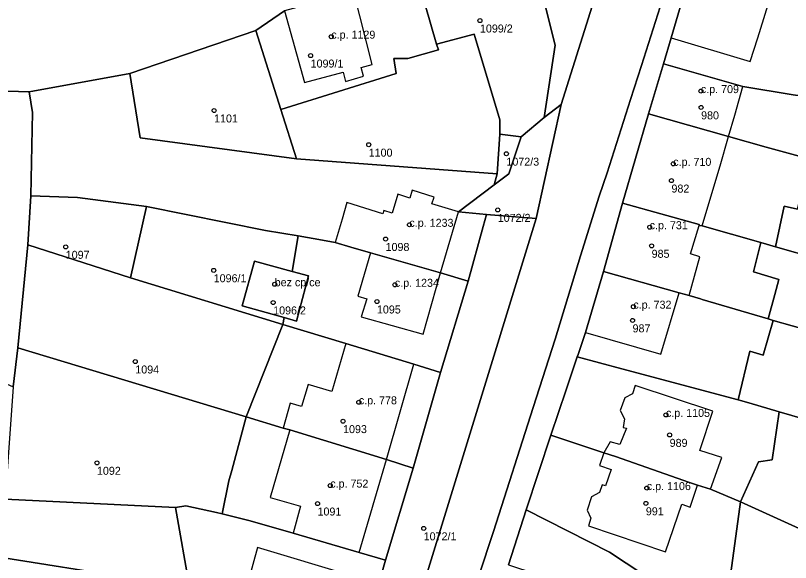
# Model space of a CAD drawing. Extents: x -878211 to -870363, y -1058464 to -1052522.
# Drawn here: x -875048.6 to -874951.8, y -1056467.9 to -1056399.5 of the extents above; entities that cross this region are included whole.
import ezdxf

# ---------------------------------------------------------------- set-up
doc = ezdxf.new("R2010")
doc.units = 0
for name, color, linetype in [('Vrstva 50', 7, 'Continuous'), ('Vrstva 51', 7, 'Continuous'), ('Vrstva 52', 7, 'Continuous')]:
    doc.layers.add(name, color=color, linetype=linetype)

msp = doc.modelspace()

# ---------------------------------------------------------------- linework, layer by layer
at = {"layer": 'Vrstva 50'}
for centre in [(-874990.58, -1056400.14994), (-875009.15, -1056402.15994), (-875011.73, -1056404.52994), (-874962.99, -1056408.95994), (-875023.79, -1056411.38994), (-874962.96, -1056410.99994), (-875004.48, -1056415.65994), (-874987.28, -1056416.78994), (-874966.44, -1056418.04994), (-874966.66, -1056420.14994), (-874988.36, -1056423.80994), (-874999.39, -1056425.66994), (-874969.38, -1056425.96994), (-875002.37, -1056427.44994), (-874969.14, -1056428.29994), (-875042.32, -1056428.42994), (-875023.84, -1056431.35994), (-875016.22, -1056433.09994), (-875001.21, -1056433.16994), (-875016.41, -1056435.37994), (-875003.45, -1056435.25994), (-874971.42, -1056435.89994), (-874971.52, -1056437.61994), (-875033.63, -1056442.75994), (-875005.71, -1056447.84994), (-874967.35, -1056449.42994), (-875007.68, -1056450.20994), (-874966.89, -1056451.92994), (-875038.42, -1056455.41994), (-875009.28, -1056458.25994), (-874969.74, -1056458.56994), (-875010.87, -1056460.50994), (-874969.86, -1056460.47994), (-874997.61, -1056463.60994)]:
    msp.add_circle(centre, 0.25, dxfattribs=at)
at = {"layer": 'Vrstva 51'}
for points in [[(-874984.08, -1056391.71), (-874981.2, -1056403.23), (-874982.58, -1056412.24), (-874980.45, -1056410.63), (-874975.13, -1056393.67), (-874976.34, -1056387.44)], [(-874927.21, -1056413.07), (-874923.91, -1056412.98), (-874926.18, -1056408.98), (-874942.27, -1056402.9), (-874949.01, -1056401.83), (-874947.24, -1056394.66), (-874952.14, -1056393.26), (-874963.08, -1056389.92), (-874966.7, -1056402.29), (-874967.66, -1056405.55), (-874957.75, -1056408.4), (-874951.48, -1056409.42), (-874947.2, -1056410.02)], [(-874984.08, -1056391.71), (-874998.25, -1056393.44), (-874997.32, -1056396.44), (-874997.44, -1056398.16), (-874995.99, -1056403.11), (-874991.31, -1056401.83), (-874988.08, -1056412.56), (-874988.12, -1056414.34), (-874985.42, -1056414.69), (-874982.58, -1056412.24), (-874981.2, -1056403.23)], [(-875015, -1056398.93), (-875018.57, -1056401.39), (-875015.44, -1056411.27), (-875001.06, -1056406.74), (-875001.34, -1056404.9), (-874999.58, -1056404.88), (-874995.78, -1056403.81), (-874995.99, -1056403.11), (-874997.44, -1056398.16), (-874997.32, -1056396.44), (-874998.25, -1056393.44), (-875002.02, -1056394.71), (-875001.89, -1056395.35), (-875006.33, -1056396.55)], [(-875018.57, -1056401.39), (-875034.3, -1056406.76), (-875033.02, -1056414.82), (-875013.49, -1056417.41), (-875015.44, -1056411.27)], [(-875013.49, -1056417.41), (-874988.44, -1056419.28), (-874988.12, -1056414.34), (-874988.08, -1056412.56), (-874991.31, -1056401.83), (-874995.99, -1056403.11), (-874995.78, -1056403.81), (-874999.58, -1056404.88), (-875001.34, -1056404.9), (-875001.06, -1056406.74), (-875015.44, -1056411.27)], [(-874947.65, -1056413.12), (-874947.2, -1056410.02), (-874951.48, -1056409.42), (-874957.75, -1056408.4), (-874967.66, -1056405.55), (-874969.53, -1056411.81), (-874959.54, -1056414.63), (-874954.84, -1056415.97), (-874950.72, -1056417.09), (-874949.95, -1056414.48), (-874949.48, -1056412.86)], [(-875017.37, -1056426.37), (-875013.27, -1056427.06), (-875010.23, -1056427.6), (-875008.66, -1056427.88), (-875006.7, -1056428.46), (-875004.26, -1056429.17), (-874995.5, -1056431.65), (-874992.07, -1056432.71), (-874990.17, -1056425.89), (-874989.75, -1056424.38), (-874993.25, -1056424.06), (-874988.8, -1056420.68), (-874988.44, -1056419.28), (-875013.49, -1056417.41), (-875033.02, -1056414.82), (-875034.3, -1056406.76), (-875046.89, -1056409.04), (-875046.48, -1056411.64), (-875046.68, -1056422.03), (-875040.87, -1056422.27), (-875032.25, -1056423.39)], [(-875046.89, -1056409.04), (-875072.36, -1056408.27), (-875075.97, -1056432.36), (-875076.17, -1056433.71), (-875048.87, -1056445.91), (-875048.32, -1056441.03), (-875047.06, -1056428.16), (-875046.68, -1056422.03), (-875046.48, -1056411.64)], [(-874986.98, -1056419.3), (-874988.8, -1056420.68), (-874993.25, -1056424.06), (-874989.75, -1056424.38), (-874983.57, -1056424.89), (-874980.45, -1056410.63), (-874982.58, -1056412.24), (-874985.42, -1056414.69)], [(-874963.22, -1056425.61), (-874963.21, -1056425.75), (-874962.81, -1056425.81), (-874955.52, -1056427.88), (-874953.65, -1056428.41), (-874952.58, -1056423.34), (-874950.93, -1056423.7), (-874950.63, -1056422.46), (-874949.3, -1056417.66), (-874950.68, -1056417.27), (-874950.72, -1056417.09), (-874954.84, -1056415.97), (-874959.54, -1056414.63), (-874969.53, -1056411.81), (-874972.76, -1056422.98)], [(-874988.44, -1056419.28), (-874988.8, -1056420.68), (-874986.98, -1056419.3), (-874985.42, -1056414.69), (-874988.12, -1056414.34)], [(-874953.65, -1056428.41), (-874932.5, -1056434.41), (-874929.49, -1056422.89), (-874950.72, -1056417.09), (-874950.68, -1056417.27), (-874949.3, -1056417.66), (-874950.63, -1056422.46), (-874950.93, -1056423.7), (-874952.58, -1056423.34)], [(-875034.25, -1056432.28), (-875032.25, -1056423.39), (-875040.87, -1056422.27), (-875046.68, -1056422.03), (-875047.06, -1056428.16)], [(-874954.58, -1056437.43), (-874953.77, -1056434.39), (-874953.27, -1056432.5), (-874956.42, -1056431.54), (-874955.52, -1056427.88), (-874962.81, -1056425.81), (-874963.21, -1056425.75), (-874963.22, -1056425.61), (-874972.76, -1056422.98), (-874975.17, -1056431.51), (-874965.68, -1056434.16), (-874964.45, -1056434.5), (-874963.05, -1056434.92), (-874962.81, -1056434.99)], [(-875014.05, -1056431.5), (-875013.27, -1056427.06), (-875017.37, -1056426.37), (-875032.25, -1056423.39), (-875034.25, -1056432.28), (-875015.2, -1056438.11), (-875015.05, -1056437.27), (-875020.29, -1056435.78), (-875018.76, -1056430.22)], [(-875005.15, -1056492.08), (-875001.65, -1056483.66), (-874983.57, -1056424.89), (-874989.75, -1056424.38), (-874990.17, -1056425.89), (-874992.07, -1056432.71), (-874995.49, -1056444.12), (-874998.92, -1056456.06), (-875002.36, -1056467.57), (-875004.97, -1056476.64), (-875007.33, -1056484.59), (-875009.05, -1056490.76), (-875012.84, -1056499.56), (-875015.72, -1056498.32), (-875017.98, -1056502.52), (-875014.85, -1056504.16), (-875019.19, -1056511.94), (-875019.42, -1056511.79), (-875024.6, -1056521.2), (-875025.16, -1056522.21), (-875025.65, -1056521.97), (-875028.12, -1056520.77), (-875035.19, -1056534.63), (-875032.55, -1056540.02)], [(-875014.05, -1056431.5), (-875011.98, -1056432.06), (-875013.51, -1056437.71), (-875015.05, -1056437.27), (-875015.2, -1056438.11), (-875007.34, -1056440.51), (-874998.84, -1056443.1), (-874995.49, -1056444.12), (-874992.07, -1056432.71), (-874995.5, -1056431.65), (-875004.26, -1056429.17), (-875006.7, -1056428.46), (-875008.66, -1056427.88), (-875010.23, -1056427.6), (-875013.27, -1056427.06)], [(-874953.97, -1056437.61), (-874934.97, -1056442.94), (-874904.61, -1056451.62), (-874902.27, -1056446.22), (-874900.82, -1056442.88), (-874932.5, -1056434.41), (-874953.65, -1056428.41), (-874955.52, -1056427.88), (-874956.42, -1056431.54), (-874953.27, -1056432.5), (-874953.77, -1056434.39), (-874954.58, -1056437.43)], [(-875034.25, -1056432.28), (-875047.06, -1056428.16), (-875048.32, -1056441.03), (-875019.78, -1056449.67), (-875015.2, -1056438.11)], [(-875015.05, -1056437.27), (-875013.51, -1056437.71), (-875011.98, -1056432.06), (-875014.05, -1056431.5), (-875018.76, -1056430.22), (-875020.29, -1056435.78)], [(-874972.87, -1056443.66), (-874958.35, -1056447.54), (-874956.89, -1056441.46), (-874955.22, -1056441.96), (-874953.97, -1056437.61), (-874954.58, -1056437.43), (-874962.81, -1056434.99), (-874963.05, -1056434.92), (-874964.45, -1056434.5), (-874965.68, -1056434.16), (-874975.17, -1056431.51), (-874977.4, -1056439.14), (-874978.33, -1056441.87), (-874978.42, -1056442.17)], [(-874936.69, -1056453.85), (-874934.97, -1056442.94), (-874953.97, -1056437.61), (-874955.22, -1056441.96), (-874956.89, -1056441.46), (-874958.35, -1056447.54), (-874957, -1056447.9), (-874953.21, -1056449.02)], [(-875007.34, -1056440.51), (-875015.2, -1056438.11), (-875019.78, -1056449.67), (-875015.15, -1056451.09), (-875014.33, -1056451.29), (-875002.24, -1056454.99), (-874998.92, -1056456.06), (-874995.49, -1056444.12), (-874998.84, -1056443.1)], [(-875048.32, -1056441.03), (-875048.87, -1056445.91), (-875049.88, -1056459.96), (-875028.63, -1056461), (-875027.33, -1056460.8), (-875023.51, -1056461.61), (-875022.78, -1056461.8), (-875021.93, -1056457.66), (-875021.57, -1056456.37), (-875019.78, -1056449.67)], [(-874975.09, -1056454.17), (-874973.64, -1056454.63), (-874964.43, -1056457.86), (-874963.39, -1056458.19), (-874961.77, -1056458.71), (-874958.06, -1056460.29), (-874955.81, -1056455.27), (-874954.08, -1056455.02), (-874953.21, -1056449.02), (-874957, -1056447.9), (-874958.35, -1056447.54), (-874972.87, -1056443.66), (-874978.42, -1056442.17), (-874979.8, -1056446.28), (-874981.75, -1056451.96)], [(-874916.64, -1056479.02), (-874915.23, -1056475.84), (-874912.43, -1056470.04), (-874909.08, -1056461.94), (-874936.69, -1056453.85), (-874953.21, -1056449.02), (-874954.08, -1056455.02), (-874955.81, -1056455.27), (-874958.06, -1056460.29), (-874927.81, -1056474.02)], [(-875019.78, -1056449.67), (-875021.57, -1056456.37), (-875021.93, -1056457.66), (-875022.78, -1056461.8), (-875019.29, -1056462.68), (-875013.9, -1056464.2), (-875005.67, -1056466.6), (-875002.36, -1056467.57), (-874998.92, -1056456.06), (-875002.24, -1056454.99), (-875014.33, -1056451.29), (-875015.15, -1056451.09)], [(-874959.23, -1056469.18), (-874958.06, -1056460.29), (-874961.77, -1056458.71), (-874963.39, -1056458.19), (-874964.43, -1056457.86), (-874973.64, -1056454.63), (-874975.09, -1056454.17), (-874981.75, -1056451.96), (-874984.83, -1056461.29), (-874974.39, -1056466.56), (-874966.18, -1056472), (-874965.81, -1056472.29), (-874962.73, -1056474.74)], [(-875026.8, -1056471.15), (-875028.63, -1056461), (-875049.88, -1056459.96), (-875068.74, -1056458.33), (-875070.13, -1056458.37), (-875070.8, -1056466.44), (-875050.07, -1056467.27), (-875034.86, -1056469.7), (-875029.7, -1056470.63)], [(-875005.67, -1056466.6), (-875013.9, -1056464.2), (-875019.29, -1056462.68), (-875022.78, -1056461.8), (-875023.51, -1056461.61), (-875027.33, -1056460.8), (-875028.63, -1056461), (-875026.8, -1056471.15), (-875017.95, -1056472.75), (-875008.34, -1056475.52), (-875004.97, -1056476.64), (-875002.36, -1056467.57)], [(-874933.12, -1056492.01), (-874924.4, -1056496.32), (-874920.02, -1056486.22), (-874916.64, -1056479.02), (-874927.81, -1056474.02), (-874958.06, -1056460.29), (-874959.23, -1056469.18), (-874962.73, -1056474.74), (-874956.59, -1056478.61), (-874948.42, -1056483.43), (-874944.97, -1056485.46), (-874942.97, -1056486.61), (-874938.77, -1056489.01)], [(-874984.83, -1056461.29), (-874987.02, -1056468.17), (-874980.32, -1056470.37), (-874982.82, -1056477.98), (-874970.83, -1056481.91), (-874966.18, -1056472), (-874974.39, -1056466.56)], [(-875071.46, -1056474.44), (-875051.87, -1056475.2), (-875047.86, -1056475.8), (-875040.01, -1056477.06), (-875037.1, -1056477.53), (-875034.86, -1056469.7), (-875050.07, -1056467.27), (-875070.8, -1056466.44)]]:
    msp.add_lwpolyline(points, close=True, dxfattribs=at)
for points in [[(-874987.02, -1056468.17), (-874984.83, -1056461.29), (-874981.75, -1056451.96), (-874979.8, -1056446.28), (-874978.42, -1056442.17), (-874978.33, -1056441.87), (-874977.4, -1056439.14), (-874975.17, -1056431.51), (-874972.76, -1056422.98), (-874969.53, -1056411.81), (-874967.66, -1056405.55), (-874966.7, -1056402.29), (-874963.08, -1056389.92)], [(-874975.13, -1056393.67), (-874980.45, -1056410.63), (-874983.57, -1056424.89), (-875001.65, -1056483.66), (-875005.15, -1056492.08), (-875032.55, -1056540.02), (-875035.19, -1056534.63), (-875039.79, -1056543.8), (-875051.68, -1056572.91), (-875052.45, -1056574.91), (-875061.84, -1056600.38), (-875067.07, -1056621.01), (-875069.87, -1056632.77), (-875075.2, -1056659.42), (-875076.83, -1056672.97), (-875088.05, -1056725.8)], [(-875104.28, -1056397.98), (-875104.23, -1056399.79), (-875097.53, -1056402.59), (-875096.93, -1056402.84), (-875072.36, -1056408.27), (-875046.89, -1056409.04), (-875034.3, -1056406.76), (-875018.57, -1056401.39), (-875015, -1056398.93)], [(-874968.09, -1056398.43), (-874970.41, -1056405.77), (-874971.79, -1056410), (-874974.71, -1056419.17), (-874975.68, -1056422.07), (-874978.03, -1056429.53), (-874981.2, -1056439.94), (-874983.94, -1056448.51), (-874988.88, -1056464.01), (-874994.3, -1056480.36)], [(-874994.3, -1056480.36), (-874988.88, -1056464.01), (-874983.94, -1056448.51), (-874981.2, -1056439.94), (-874978.03, -1056429.53), (-874975.68, -1056422.07), (-874974.71, -1056419.17), (-874971.79, -1056410), (-874970.41, -1056405.77), (-874968.09, -1056398.43)]]:
    msp.add_lwpolyline(points, dxfattribs=at)
at = {"layer": 'Vrstva 52'}
for points in [[(-874966.7, -1056402.29), (-874956.82, -1056405.26), (-874955.88, -1056402.32), (-874954.2, -1056396.87), (-874953.14, -1056393.36), (-874952.26, -1056393.63), (-874952.14, -1056393.26), (-874963.08, -1056389.92)], [(-875015, -1056398.93), (-875012.5, -1056407.9), (-875007.67, -1056406.58), (-875007.36, -1056407.74), (-875005.13, -1056407.08), (-875005.43, -1056406.02), (-875004.05, -1056405.64), (-875006.33, -1056396.55)], [(-874957.75, -1056408.4), (-874967.66, -1056405.55), (-874969.53, -1056411.81), (-874959.54, -1056414.63), (-874958.73, -1056411.98)], [(-874962.36, -1056424.26), (-874960.59, -1056418.31), (-874959.54, -1056414.63), (-874969.53, -1056411.81), (-874972.76, -1056422.98), (-874963.22, -1056425.61), (-874963.21, -1056425.75), (-874962.81, -1056425.81)], [(-875007.81, -1056424.97), (-875008.66, -1056427.88), (-875006.7, -1056428.46), (-875004.26, -1056429.17), (-874995.5, -1056431.65), (-874993.25, -1056424.06), (-874996.58, -1056423.04), (-874996.31, -1056422.21), (-874999.05, -1056421.36), (-874999.34, -1056422.32), (-875000.84, -1056421.86), (-875001.55, -1056424.2), (-875002.59, -1056423.88), (-875002.72, -1056424.31), (-875007.2, -1056422.9)], [(-874972.76, -1056422.98), (-874975.17, -1056431.51), (-874965.68, -1056434.16), (-874964.45, -1056434.5), (-874963.13, -1056429.66), (-874964.27, -1056429.29), (-874963.21, -1056425.75), (-874963.22, -1056425.61)], [(-874997.69, -1056439.32), (-874995.5, -1056431.65), (-875004.26, -1056429.17), (-875005.84, -1056434.57), (-875004.73, -1056434.91), (-875005.4, -1056437.17)], [(-875020.29, -1056435.78), (-875015.05, -1056437.27), (-875013.51, -1056437.71), (-875011.98, -1056432.06), (-875014.05, -1056431.5), (-875018.76, -1056430.22)], [(-874975.17, -1056431.51), (-874977.4, -1056439.14), (-874967.98, -1056441.85), (-874965.68, -1056434.16)], [(-875015.15, -1056451.09), (-875014.33, -1056451.29), (-875002.24, -1056454.99), (-874998.84, -1056443.1), (-875007.34, -1056440.51), (-875009.08, -1056446.48), (-875012.04, -1056445.61), (-875012.86, -1056448.37), (-875014.27, -1056447.96)], [(-874974.31, -1056452.77), (-874975.09, -1056454.17), (-874973.64, -1056454.63), (-874964.43, -1056457.86), (-874963.39, -1056458.19), (-874961.77, -1056458.71), (-874960.39, -1056454.76), (-874963.11, -1056453.87), (-874961.48, -1056448.95), (-874971.18, -1056445.73), (-874971.54, -1056446.79), (-874972.5, -1056447.28), (-874973.05, -1056448.88), (-874972.53, -1056449.92), (-874972.7, -1056450.98), (-874972.27, -1056451.09), (-874973.13, -1056453.11)], [(-875016.78, -1056459.76), (-875012.98, -1056460.82), (-875013.9, -1056464.2), (-875005.67, -1056466.6), (-875002.24, -1056454.99), (-875014.33, -1056451.29)], [(-874975.09, -1056454.17), (-874975.66, -1056455.75), (-874974.2, -1056456.25), (-874974.89, -1056458.29), (-874975.31, -1056458.17), (-874975.64, -1056459.12), (-874976.65, -1056459.65), (-874977.2, -1056461.31), (-874976.74, -1056462.34), (-874977.03, -1056463.3), (-874967.4, -1056466.53), (-874965.36, -1056460.59), (-874964.32, -1056460.95), (-874963.39, -1056458.19), (-874964.43, -1056457.86), (-874973.64, -1056454.63)], [(-875019.41, -1056469.79), (-875017.29, -1056470.36), (-875017.95, -1056472.75), (-875008.34, -1056475.52), (-875006.57, -1056469.54), (-875018.38, -1056466.01)]]:
    msp.add_lwpolyline(points, close=True, dxfattribs=at)

# ---------------------------------------------------------------- texts
at = {"layer": 'Vrstva 50'}
for s, p in [('1099/2', (-874990.58, -1056401.639)), ('c.p. 1129', (-875009.15, -1056402.409)), ('1099/1', (-875011.73, -1056406.019)), ('c.p. 709', (-874962.99, -1056409.21)), ('980', (-874962.96, -1056412.489)), ('1101', (-875023.79, -1056412.879)), ('1100', (-875004.48, -1056417.149)), ('1072/3', (-874987.28, -1056418.279)), ('c.p. 710', (-874966.44, -1056418.3)), ('982', (-874966.66, -1056421.639)), ('1072/2', (-874988.36, -1056425.299)), ('c.p. 1233', (-874999.39, -1056425.919)), ('c.p. 731', (-874969.38, -1056426.22)), ('1098', (-875002.37, -1056428.939)), ('1097', (-875042.32, -1056429.919)), ('985', (-874969.14, -1056429.789)), ('1096/1', (-875023.84, -1056432.849)), ('bez cp/ce', (-875016.22, -1056433.35)), ('c.p. 1234', (-875001.21, -1056433.419)), ('1096/2', (-875016.41, -1056436.869)), ('1095', (-875003.45, -1056436.749)), ('c.p. 732', (-874971.42, -1056436.149)), ('987', (-874971.52, -1056439.109)), ('1094', (-875033.63, -1056444.249)), ('c.p. 778', (-875005.71, -1056448.1)), ('c.p. 1105', (-874967.35, -1056449.679)), ('1093', (-875007.68, -1056451.699)), ('989', (-874966.89, -1056453.419)), ('1092', (-875038.42, -1056456.909)), ('c.p. 752', (-875009.28, -1056458.51)), ('c.p. 1106', (-874969.74, -1056458.82)), ('1091', (-875010.87, -1056461.999)), ('991', (-874969.86, -1056461.969)), ('1072/1', (-874997.61, -1056465.099))]:
    msp.add_text(s, height=0.999996, dxfattribs=at).set_placement(p)

doc.saveas('drawing.dxf')
